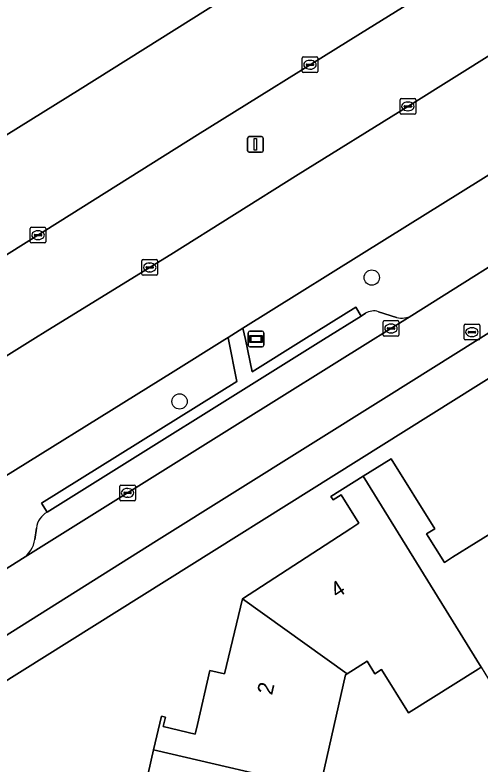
# Model space of a CAD drawing. Extents: x 157767 to 159172, y 387839 to 389425.
# Drawn here: x 158267.74 to 158297.49, y 388222.82 to 388270.73 of the extents above; entities that cross this region are included whole.
import ezdxf

# ---------------------------------------------------------------- set-up
doc = ezdxf.new("R2010")
doc.units = 0
for name, color, linetype in [('IMGEO_Berm_groen', 7, 'Continuous'), ('IMGEO_Boom', 7, 'Continuous'), ('IMGEO_Erf', 7, 'Continuous'), ('IMGEO_Informatiebord', 7, 'Continuous'), ('IMGEO_Kolk', 7, 'Continuous'), ('IMGEO_Lichtmast', 7, 'Continuous'), ('IMGEO_Pand', 7, 'Continuous'), ('IMGEO_Pand_nummerreeks', 7, 'Continuous'), ('IMGEO_Parkeervlak_open', 7, 'Continuous'), ('IMGEO_Rijbaan_lokaal_gesloten', 7, 'Continuous'), ('IMGEO_Rijbaan_lokaal_open', 7, 'Continuous'), ('IMGEO_Rioolput', 7, 'Continuous'), ('IMGEO_Voetpad_open', 7, 'Continuous')]:
    doc.layers.add(name, color=color, linetype=linetype)

msp = doc.modelspace()

# ---------------------------------------------------------------- linework, layer by layer
at = {"layer": 'IMGEO_Berm_groen'}
msp.add_lwpolyline([(158301.424, 388270.224), (158311.965, 388276.829), (158320.172, 388281.961), (158323.39, 388283.962), (158320.427, 388288.517), (158318.918, 388287.723), (158311.051, 388282.809), (158301.132, 388276.553), (158289.832, 388269.56), (158279.411, 388263.075), (158270.632, 388257.554), (158260.49, 388251.216), (158258.547, 388250), (158253.486, 388246.832), (158256.361, 388242.184), (158261.994, 388245.734), (158268.881, 388250), (158269.832, 388250.589), (158277.711, 388255.433), (158285.85, 388260.547), (158292.876, 388264.893)], close=True, dxfattribs=at)
for points in [[(158271.906, 388265.997), (158284.109, 388273.656), (158293.929, 388279.825), (158292.328, 388282.456), (158283.833, 388284.506), (158247.662, 388262.433), (158245.424, 388266.158), (158233.501, 388258.911), (158232.551, 388250.756), (158231.308, 388250), (158218.642, 388242.296)], [(158331.262, 388278.203), (158328.583, 388276.523), (158327.166, 388278.678), (158318.32, 388273.151), (158304.666, 388264.637), (158291.553, 388256.471), (158282.323, 388250.72), (158282.475, 388250), (158282.911, 388247.934), (158286.225, 388250), (158289.534, 388252.063), (158289.883, 388251.504), (158290.16, 388251.676)], [(158218.481, 388241.599), (158222.599, 388235.192), (158235.601, 388243.333), (158240.03, 388246.171), (158242.941, 388247.95), (158246.245, 388250), (158253.604, 388254.566), (158262.426, 388260.118), (158271.906, 388265.997)], [(158293.133, 388251.542), (158301.805, 388256.984)], [(158290.991, 388251.781), (158292.136, 388251.417)], [(158269.792, 388238.979), (158269.443, 388239.539), (158281.935, 388247.326), (158281.394, 388250), (158281.369, 388250.126), (158281.167, 388250), (158277.869, 388247.946), (158264.594, 388239.709), (158248.555, 388229.66), (158234.236, 388220.596), (158232.504, 388219.327), (158233.735, 388217.461), (158234.536, 388216.285), (158239.139, 388219.222), (158248.541, 388225.022)], [(158269.012, 388237.232), (158269.11, 388237.956)], [(158267.18, 388235.363), (158268.231, 388236.02)]]:
    msp.add_lwpolyline(points, dxfattribs=at)
for centre, radius, start, end in [((158290.689, 388250.831), 0.997, 72.3649, 122.0379), ((158292.484, 388252.678), 1.309, 254.5699, 299.7226), ((158270.501, 388237.767), 1.404, 120.3452, 172.2746), ((158267.325, 388237.461), 1.702, 302.1481, 352.2573)]:
    msp.add_arc(centre, radius, start, end, dxfattribs=at)
at = {"layer": 'IMGEO_Boom'}
for centre in [(158290.561, 388253.957), (158278.268, 388246.043)]:
    msp.add_circle(centre, 0.489, dxfattribs=at)
at = {"layer": 'IMGEO_Erf'}
for points in [[(158302.018, 388250), (158263.543, 388225.936)], [(158282.297, 388233.442), (158289.223, 388237.932), (158289.745, 388238.271), (158288.613, 388240.08), (158288.086, 388239.751), (158287.943, 388239.979), (158290.018, 388241.277), (158291.798, 388242.39), (158294.597, 388237.914), (158294.073, 388237.586), (158295.212, 388235.764), (158295.736, 388236.092), (158298.757, 388237.981)], [(158276.065, 388221.436), (158276.607, 388223.785), (158277.103, 388225.936), (158277.367, 388225.876), (158277.228, 388225.272), (158279.274, 388224.801), (158279.413, 388225.404), (158280.209, 388228.859), (158281.14, 388228.644), (158282.297, 388233.442)], [(158297.552, 388229.065), (158297.362, 388228.946), (158292.915, 388226.164), (158291.194, 388228.915), (158290.762, 388228.645), (158290.26, 388229.448), (158288.985, 388228.65), (158288.882, 388228.585), (158287.241, 388221.328)]]:
    msp.add_lwpolyline(points, dxfattribs=at)
at = {"layer": 'IMGEO_Informatiebord'}
for p, q in [((158282.665, 388249.634), (158282.665, 388250.434)), ((158282.665, 388250.434), (158282.665, 388249.634)), ((158282.765, 388250.534), (158283.555, 388250.534)), ((158283.555, 388250.534), (158282.765, 388250.534)), ((158283.655, 388250.434), (158283.655, 388249.634)), ((158283.655, 388249.634), (158283.655, 388250.434)), ((158283.555, 388249.534), (158282.765, 388249.534)), ((158282.765, 388249.534), (158283.555, 388249.534))]:
    msp.add_line(p, q, dxfattribs=at)
for points in [[(158282.766, 388250.266), (158283.554, 388250.266), (158283.554, 388249.802), (158282.766, 388249.802), (158282.766, 388250.266)], [(158282.831, 388250.201), (158282.831, 388249.867), (158283.489, 388249.867), (158283.489, 388250.201), (158282.831, 388250.201)]]:
    msp.add_lwpolyline(points, dxfattribs=at)
for centre, start, end in [((158282.765, 388250.434), 90, 180), ((158282.765, 388250.434), 90, 180), ((158283.555, 388250.434), 0, 90), ((158283.555, 388250.434), 360, 90), ((158282.765, 388249.634), 180, 270), ((158282.765, 388249.634), 180, 270), ((158283.555, 388249.634), 270, 0), ((158283.555, 388249.634), 270, 0)]:
    msp.add_arc(centre, 0.1, start, end, dxfattribs=at)
at = {"layer": 'IMGEO_Kolk'}
for p, q in [((158286.107, 388267.127), (158286.107, 388267.979)), ((158286.182, 388268.053), (158287.034, 388268.053)), ((158287.108, 388267.979), (158287.108, 388267.127)), ((158286.366, 388267.547), (158286.366, 388267.559)), ((158286.804, 388267.51), (158286.406, 388267.51)), ((158286.409, 388267.596), (158286.807, 388267.596)), ((158286.595, 388267.833), (158286.62, 388267.833)), ((158286.85, 388267.559), (158286.85, 388267.547)), ((158287.034, 388267.053), (158286.182, 388267.053)), ((158286.618, 388267.273), (158286.593, 388267.273)), ((158292.373, 388264.467), (158292.373, 388265.319)), ((158292.448, 388265.393), (158293.3, 388265.393)), ((158292.861, 388265.173), (158292.886, 388265.173)), ((158293.374, 388265.319), (158293.374, 388264.467)), ((158292.632, 388264.887), (158292.632, 388264.899)), ((158293.07, 388264.85), (158292.672, 388264.85)), ((158292.675, 388264.936), (158293.073, 388264.936)), ((158292.884, 388264.613), (158292.859, 388264.613)), ((158293.116, 388264.899), (158293.116, 388264.887)), ((158293.3, 388264.393), (158292.448, 388264.393)), ((158268.717, 388256.243), (158268.717, 388257.095)), ((158268.792, 388257.169), (158269.644, 388257.169)), ((158269.205, 388256.949), (158269.23, 388256.949)), ((158269.718, 388257.095), (158269.718, 388256.243)), ((158268.976, 388256.663), (158268.976, 388256.675)), ((158269.414, 388256.626), (158269.016, 388256.626)), ((158269.019, 388256.712), (158269.417, 388256.712)), ((158269.46, 388256.675), (158269.46, 388256.663)), ((158269.644, 388256.169), (158268.792, 388256.169)), ((158269.228, 388256.389), (158269.203, 388256.389)), ((158275.861, 388254.179), (158275.861, 388255.031)), ((158275.936, 388255.105), (158276.788, 388255.105)), ((158276.862, 388255.031), (158276.862, 388254.179)), ((158276.12, 388254.599), (158276.12, 388254.611)), ((158276.558, 388254.562), (158276.16, 388254.562)), ((158276.163, 388254.648), (158276.561, 388254.648)), ((158276.349, 388254.885), (158276.374, 388254.885)), ((158276.604, 388254.611), (158276.604, 388254.599)), ((158276.788, 388254.105), (158275.936, 388254.105)), ((158276.372, 388254.325), (158276.347, 388254.325)), ((158291.365, 388251.207), (158292.217, 388251.207)), ((158291.29, 388250.281), (158291.29, 388251.133)), ((158291.549, 388250.701), (158291.549, 388250.713)), ((158291.592, 388250.75), (158291.99, 388250.75)), ((158291.778, 388250.987), (158291.803, 388250.987)), ((158292.033, 388250.713), (158292.033, 388250.701)), ((158292.291, 388251.133), (158292.291, 388250.281)), ((158291.987, 388250.664), (158291.589, 388250.664)), ((158291.801, 388250.427), (158291.776, 388250.427)), ((158292.217, 388250.207), (158291.365, 388250.207)), ((158274.515, 388240.705), (158275.367, 388240.705)), ((158274.44, 388239.779), (158274.44, 388240.631)), ((158274.699, 388240.199), (158274.699, 388240.211)), ((158274.742, 388240.248), (158275.14, 388240.248)), ((158274.928, 388240.485), (158274.953, 388240.485)), ((158275.183, 388240.211), (158275.183, 388240.199)), ((158275.441, 388240.631), (158275.441, 388239.779)), ((158275.367, 388239.705), (158274.515, 388239.705)), ((158275.137, 388240.162), (158274.739, 388240.162)), ((158274.951, 388239.925), (158274.926, 388239.925))]:
    msp.add_line(p, q, dxfattribs=at)
for points in [[(158286.107, 388267.127), (158286.107, 388267.979)], [(158286.182, 388268.053), (158287.034, 388268.053)], [(158287.108, 388267.979), (158287.108, 388267.127)], [(158287.034, 388267.053), (158286.182, 388267.053)], [(158292.373, 388264.467), (158292.373, 388265.319)], [(158292.448, 388265.393), (158293.3, 388265.393)], [(158293.374, 388265.319), (158293.374, 388264.467)], [(158293.3, 388264.393), (158292.448, 388264.393)], [(158268.717, 388256.243), (158268.717, 388257.095)], [(158268.792, 388257.169), (158269.644, 388257.169)], [(158269.718, 388257.095), (158269.718, 388256.243)], [(158269.644, 388256.169), (158268.792, 388256.169)], [(158275.861, 388254.179), (158275.861, 388255.031)], [(158275.936, 388255.105), (158276.788, 388255.105)], [(158276.862, 388255.031), (158276.862, 388254.179)], [(158276.788, 388254.105), (158275.936, 388254.105)], [(158291.365, 388251.207), (158292.217, 388251.207)], [(158291.29, 388250.281), (158291.29, 388251.133)], [(158292.291, 388251.133), (158292.291, 388250.281)], [(158292.217, 388250.207), (158291.365, 388250.207)], [(158274.515, 388240.705), (158275.367, 388240.705)], [(158274.44, 388239.779), (158274.44, 388240.631)], [(158275.441, 388240.631), (158275.441, 388239.779)], [(158275.367, 388239.705), (158274.515, 388239.705)]]:
    msp.add_lwpolyline(points, dxfattribs=at)
for centre, radius, start, end in [((158286.184, 388267.977), 0.0765, 91.552, 178.448), ((158286.184, 388267.977), 0.0765, 91.552, 178.448), ((158287.032, 388267.977), 0.0765, 1.552, 88.448), ((158287.032, 388267.977), 0.0765, 1.552, 88.448), ((158286.406, 388267.556), 0.0403, 85.8775, 175.7526), ((158286.403, 388267.546), 0.0366, 178.938, 274.7102), ((158286.807, 388267.553), 0.043, 264.8664, 352.4533), ((158286.811, 388267.558), 0.0386, 1.7309, 96.639), ((158286.184, 388267.129), 0.0765, 181.552, 268.448), ((158286.184, 388267.129), 0.0765, 181.552, 268.448), ((158287.032, 388267.129), 0.0765, 271.552, 358.448), ((158287.032, 388267.129), 0.0765, 271.552, 358.448), ((158292.45, 388265.317), 0.0765, 91.552, 178.448), ((158292.45, 388265.317), 0.0765, 91.552, 178.448), ((158293.298, 388265.317), 0.0765, 1.552, 88.448), ((158293.298, 388265.317), 0.0765, 1.552, 88.448), ((158292.672, 388264.896), 0.0403, 85.8775, 175.7526), ((158292.669, 388264.886), 0.0366, 178.938, 274.7102), ((158293.073, 388264.893), 0.043, 264.8664, 352.4533), ((158293.077, 388264.898), 0.0386, 1.7309, 96.639), ((158292.45, 388264.469), 0.0765, 181.552, 268.448), ((158292.45, 388264.469), 0.0765, 181.552, 268.448), ((158293.298, 388264.469), 0.0765, 271.552, 358.448), ((158293.298, 388264.469), 0.0765, 271.552, 358.448), ((158268.794, 388257.093), 0.0765, 91.552, 178.448), ((158268.794, 388257.093), 0.0765, 91.552, 178.448), ((158269.642, 388257.093), 0.0765, 1.552, 88.448), ((158269.642, 388257.093), 0.0765, 1.552, 88.448), ((158269.016, 388256.672), 0.0403, 85.8775, 175.7526), ((158269.013, 388256.662), 0.0366, 178.938, 274.7102), ((158269.417, 388256.669), 0.043, 264.8664, 352.4533), ((158269.421, 388256.674), 0.0386, 1.7309, 96.639), ((158268.794, 388256.245), 0.0765, 181.552, 268.448), ((158268.794, 388256.245), 0.0765, 181.552, 268.448), ((158269.642, 388256.245), 0.0765, 271.552, 358.448), ((158269.642, 388256.245), 0.0765, 271.552, 358.448), ((158275.938, 388255.029), 0.0765, 91.552, 178.448), ((158275.938, 388255.029), 0.0765, 91.552, 178.448), ((158276.786, 388255.029), 0.0765, 1.552, 88.448), ((158276.786, 388255.029), 0.0765, 1.552, 88.448), ((158276.16, 388254.608), 0.0403, 85.8775, 175.7526), ((158276.157, 388254.598), 0.0366, 178.938, 274.7102), ((158276.561, 388254.605), 0.043, 264.8664, 352.4533), ((158276.565, 388254.61), 0.0386, 1.7309, 96.639), ((158275.938, 388254.181), 0.0765, 181.552, 268.448), ((158275.938, 388254.181), 0.0765, 181.552, 268.448), ((158276.786, 388254.181), 0.0765, 271.552, 358.448), ((158276.786, 388254.181), 0.0765, 271.552, 358.448), ((158291.367, 388251.131), 0.0765, 91.552, 178.448), ((158291.367, 388251.131), 0.0765, 91.552, 178.448), ((158292.215, 388251.131), 0.0765, 1.552, 88.448), ((158292.215, 388251.131), 0.0765, 1.552, 88.448), ((158291.589, 388250.71), 0.0403, 85.8775, 175.7526), ((158291.994, 388250.712), 0.0386, 1.7309, 96.639), ((158291.367, 388250.283), 0.0765, 181.552, 268.448), ((158291.367, 388250.283), 0.0765, 181.552, 268.448), ((158291.586, 388250.7), 0.0366, 178.938, 274.7102), ((158291.99, 388250.707), 0.043, 264.8664, 352.4533), ((158292.215, 388250.283), 0.0765, 271.552, 358.448), ((158292.215, 388250.283), 0.0765, 271.552, 358.448), ((158274.517, 388240.629), 0.0765, 91.552, 178.448), ((158274.517, 388240.629), 0.0765, 91.552, 178.448), ((158275.365, 388240.629), 0.0765, 1.552, 88.448), ((158275.365, 388240.629), 0.0765, 1.552, 88.448), ((158274.739, 388240.208), 0.0403, 85.8775, 175.7526), ((158274.736, 388240.198), 0.0366, 178.938, 274.7102), ((158275.14, 388240.205), 0.043, 264.8664, 352.4533), ((158275.144, 388240.21), 0.0386, 1.7309, 96.639), ((158274.517, 388239.781), 0.0765, 181.552, 268.448), ((158274.517, 388239.781), 0.0765, 181.552, 268.448), ((158275.365, 388239.781), 0.0765, 271.552, 358.448), ((158275.365, 388239.781), 0.0765, 271.552, 358.448)]:
    msp.add_arc(centre, radius, start, end, dxfattribs=at)
for centre, major_axis, ratio, start_param, end_param in [((158286.594, 388267.553), (-0.387, 0.002), 0.722429, 4.712389, 7.853982), ((158286.619, 388267.553), (-0.39, 0.002), 0.717154, 1.570796, 4.712389), ((158292.86, 388264.893), (-0.387, 0.002), 0.722429, 4.712389, 7.853982), ((158292.885, 388264.893), (-0.39, 0.002), 0.717154, 1.570796, 4.712389), ((158269.204, 388256.669), (-0.387, 0.002), 0.722429, 4.712389, 7.853982), ((158269.229, 388256.669), (-0.39, 0.002), 0.717154, 1.570796, 4.712389), ((158276.348, 388254.605), (-0.387, 0.002), 0.722429, 4.712389, 7.853982), ((158276.373, 388254.605), (-0.39, 0.002), 0.717154, 1.570796, 4.712389), ((158291.777, 388250.707), (-0.387, 0.002), 0.722429, 4.712389, 7.853982), ((158291.802, 388250.707), (-0.39, 0.002), 0.717154, 1.570796, 4.712389), ((158274.927, 388240.205), (-0.387, 0.002), 0.722429, 4.712389, 7.853982), ((158274.952, 388240.205), (-0.39, 0.002), 0.717154, 1.570796, 4.712389)]:
    msp.add_ellipse(centre, major_axis=major_axis, ratio=ratio, start_param=start_param, end_param=end_param, dxfattribs=at)
at = {"layer": 'IMGEO_Lichtmast'}
for p, q in [((158282.623, 388262.065), (158282.623, 388262.865)), ((158282.623, 388262.865), (158282.623, 388262.065)), ((158282.723, 388262.965), (158283.513, 388262.965)), ((158283.513, 388262.965), (158282.723, 388262.965)), ((158283.613, 388262.865), (158283.613, 388262.065)), ((158283.613, 388262.065), (158283.613, 388262.865)), ((158283.513, 388261.965), (158282.723, 388261.965)), ((158282.723, 388261.965), (158283.513, 388261.965))]:
    msp.add_line(p, q, dxfattribs=at)
msp.add_lwpolyline([(158283.043, 388262.84), (158283.193, 388262.84), (158283.193, 388262.09), (158283.043, 388262.09), (158283.043, 388262.84)], dxfattribs=at)
for centre, start, end in [((158282.723, 388262.865), 90, 180), ((158282.723, 388262.865), 90, 180), ((158283.513, 388262.865), 0, 90), ((158283.513, 388262.865), 360, 90), ((158282.723, 388262.065), 180, 270), ((158282.723, 388262.065), 180, 270), ((158283.513, 388262.065), 270, 0), ((158283.513, 388262.065), 270, 0)]:
    msp.add_arc(centre, 0.1, start, end, dxfattribs=at)
at = {"layer": 'IMGEO_Pand'}
for points in [[(158298.757, 388237.981), (158295.736, 388236.092), (158295.212, 388235.764), (158294.073, 388237.586), (158294.597, 388237.914), (158291.798, 388242.39), (158290.018, 388241.277), (158297.552, 388229.065), (158298.491, 388227.543), (158303.363, 388230.59)], [(158290.018, 388241.277), (158287.943, 388239.979), (158288.086, 388239.751), (158288.613, 388240.08), (158289.745, 388238.271), (158289.223, 388237.932), (158282.297, 388233.442), (158288.985, 388228.65), (158290.26, 388229.448), (158290.762, 388228.645), (158291.194, 388228.915), (158292.915, 388226.164), (158297.362, 388228.946), (158297.552, 388229.065)], [(158287.241, 388221.328), (158288.882, 388228.585), (158288.985, 388228.65), (158282.297, 388233.442), (158281.14, 388228.644), (158280.209, 388228.859), (158279.413, 388225.404), (158279.274, 388224.801), (158277.228, 388225.272), (158277.367, 388225.876), (158277.103, 388225.936), (158276.607, 388223.785)], [(158287.241, 388221.328), (158276.607, 388223.785), (158276.065, 388221.436), (158276.329, 388221.375), (158276.469, 388221.981), (158278.543, 388221.503), (158278.403, 388220.897), (158277.604, 388217.429), (158278.492, 388217.224), (158277.43, 388212.613), (158285.582, 388213.989)]]:
    msp.add_lwpolyline(points, close=True, dxfattribs=at)
at = {"layer": 'IMGEO_Parkeervlak_open'}
for points in [[(158290.16, 388251.676), (158289.883, 388251.504), (158287.47, 388250), (158269.792, 388238.979)], [(158292.136, 388251.417), (158290.991, 388251.781)], [(158268.231, 388236.02), (158281.966, 388244.585), (158290.658, 388250), (158293.133, 388251.542)], [(158269.11, 388237.956), (158269.012, 388237.232)]]:
    msp.add_lwpolyline(points, dxfattribs=at)
for centre, radius, start, end in [((158290.689, 388250.831), 0.997, 72.3649, 122.0379), ((158292.484, 388252.678), 1.309, 254.5699, 299.7226), ((158270.501, 388237.767), 1.404, 120.3452, 172.2746), ((158267.325, 388237.461), 1.702, 302.1481, 352.2573)]:
    msp.add_arc(centre, radius, start, end, dxfattribs=at)
at = {"layer": 'IMGEO_Rijbaan_lokaal_gesloten'}
for points in [[(158340.574, 388308.966), (158338.044, 388307.393), (158335.487, 388305.815), (158329.232, 388301.865), (158325.841, 388299.724), (158323.243, 388298.097), (158319.303, 388295.635), (158318.479, 388295.12), (158316.732, 388294.034), (158307.259, 388288.147), (158296.76, 388281.603), (158293.929, 388279.825), (158284.109, 388273.656), (158271.906, 388265.997), (158262.426, 388260.118), (158253.604, 388254.566), (158246.245, 388250), (158242.941, 388247.95), (158240.03, 388246.171), (158235.601, 388243.333), (158222.599, 388235.192), (158221.83, 388234.711)], [(158214.777, 388233.188), (158219.655, 388225.675), (158221.791, 388227.034), (158222.686, 388227.604), (158225.956, 388229.686), (158228.439, 388231.238), (158233.827, 388234.591), (158241.948, 388239.696), (158252.21, 388246.033), (158253.486, 388246.832), (158258.547, 388250), (158260.49, 388251.216), (158270.632, 388257.554), (158279.411, 388263.075), (158289.832, 388269.56), (158301.132, 388276.553), (158311.051, 388282.809), (158318.918, 388287.723), (158320.427, 388288.517), (158344.078, 388303.351), (158344.366, 388303.567), (158346.538, 388304.917), (158349.427, 388306.68)], [(158232.504, 388219.327), (158234.236, 388220.596), (158248.555, 388229.66), (158264.594, 388239.709), (158277.869, 388247.946), (158281.167, 388250), (158281.369, 388250.126), (158282.323, 388250.72), (158291.553, 388256.471), (158304.666, 388264.637), (158318.32, 388273.151), (158327.166, 388278.678), (158329.789, 388280.317), (158345.174, 388289.863), (158347.634, 388291.422), (158350.21, 388293.055), (158351.701, 388294), (158356.997, 388297.192), (158363.613, 388301.064)], [(158326.908, 388286.149), (158325.945, 388285.55), (158323.39, 388283.962), (158320.172, 388281.961), (158311.965, 388276.829), (158301.424, 388270.224), (158292.876, 388264.893), (158285.85, 388260.547), (158277.711, 388255.433), (158269.832, 388250.589), (158268.881, 388250), (158261.994, 388245.734), (158256.361, 388242.184), (158254.243, 388240.849), (158245.553, 388235.376), (158238.633, 388231.098), (158230.073, 388225.616), (158228.915, 388224.902), (158225.581, 388222.844), (158224.726, 388222.317), (158222.611, 388221.012), (158228.422, 388211.077), (158228.678, 388212.844)]]:
    msp.add_lwpolyline(points, dxfattribs=at)
at = {"layer": 'IMGEO_Rijbaan_lokaal_open'}
for points in [[(158291.485, 388246.325), (158297.376, 388250), (158306.522, 388255.727), (158304.635, 388258.774), (158301.805, 388256.984), (158293.133, 388251.542), (158290.658, 388250), (158281.966, 388244.585), (158268.231, 388236.02), (158267.18, 388235.363), (158257.508, 388229.254)], [(158262.381, 388228.103), (158276.788, 388237.133), (158291.485, 388246.325)]]:
    msp.add_lwpolyline(points, dxfattribs=at)
at = {"layer": 'IMGEO_Rioolput'}
for p, q in [((158296.467, 388250.047), (158296.467, 388250.899)), ((158296.542, 388250.973), (158297.394, 388250.973)), ((158296.955, 388250.753), (158296.98, 388250.753)), ((158297.468, 388250.899), (158297.468, 388250.047)), ((158296.726, 388250.467), (158296.726, 388250.479)), ((158297.164, 388250.43), (158296.766, 388250.43)), ((158296.769, 388250.516), (158297.167, 388250.516)), ((158297.21, 388250.479), (158297.21, 388250.467)), ((158297.394, 388249.973), (158296.542, 388249.973)), ((158296.978, 388250.193), (158296.953, 388250.193))]:
    msp.add_line(p, q, dxfattribs=at)
for points in [[(158296.467, 388250.047), (158296.467, 388250.899)], [(158296.542, 388250.973), (158297.394, 388250.973)], [(158297.468, 388250.899), (158297.468, 388250.047)], [(158297.394, 388249.973), (158296.542, 388249.973)]]:
    msp.add_lwpolyline(points, dxfattribs=at)
for centre, radius, start, end in [((158296.544, 388250.897), 0.0765, 91.552, 178.448), ((158296.544, 388250.897), 0.0765, 91.552, 178.448), ((158297.392, 388250.897), 0.0765, 1.552, 88.448), ((158297.392, 388250.897), 0.0765, 1.552, 88.448), ((158296.766, 388250.476), 0.0403, 85.8775, 175.7526), ((158296.763, 388250.466), 0.0366, 178.938, 274.7102), ((158297.167, 388250.473), 0.043, 264.8664, 352.4533), ((158297.171, 388250.478), 0.0386, 1.7309, 96.639), ((158296.544, 388250.049), 0.0765, 181.552, 268.448), ((158296.544, 388250.049), 0.0765, 181.552, 268.448), ((158297.392, 388250.049), 0.0765, 271.552, 358.448), ((158297.392, 388250.049), 0.0765, 271.552, 358.448)]:
    msp.add_arc(centre, radius, start, end, dxfattribs=at)
for centre, major_axis, ratio, start_param, end_param in [((158296.954, 388250.473), (-0.387, 0.002), 0.722429, 4.712389, 7.853982), ((158296.979, 388250.473), (-0.39, 0.002), 0.717154, 1.570796, 4.712389)]:
    msp.add_ellipse(centre, major_axis=major_axis, ratio=ratio, start_param=start_param, end_param=end_param, dxfattribs=at)
at = {"layer": 'IMGEO_Voetpad_open'}
for points in [[(158336.27, 388276.303), (158338.282, 388273.157), (158332.269, 388269.479), (158316.929, 388262.243), (158308.753, 388257.124), (158308.108, 388256.72), (158306.522, 388255.727), (158297.376, 388250), (158291.485, 388246.325), (158276.788, 388237.133), (158262.381, 388228.103)], [(158258.442, 388222.823), (158263.005, 388225.652), (158263.543, 388225.936), (158302.018, 388250), (158318.434, 388260.267)]]:
    msp.add_lwpolyline(points, dxfattribs=at)
msp.add_lwpolyline([(158289.883, 388251.504), (158289.534, 388252.063), (158286.225, 388250), (158282.911, 388247.934), (158282.475, 388250), (158282.323, 388250.72), (158281.369, 388250.126), (158281.394, 388250), (158281.935, 388247.326), (158269.443, 388239.539), (158269.792, 388238.979), (158287.47, 388250)], close=True, dxfattribs=at)

# ---------------------------------------------------------------- texts
at = {"layer": 'IMGEO_Pand_nummerreeks'}
for s, rotation, p in [('4', 32.9565, (158288.333, 388233.448)), ('2', 77.0195, (158284.184, 388227.247))]:
    msp.add_text(s, height=1, rotation=rotation, dxfattribs=at).set_placement(p)

doc.saveas('drawing.dxf')
